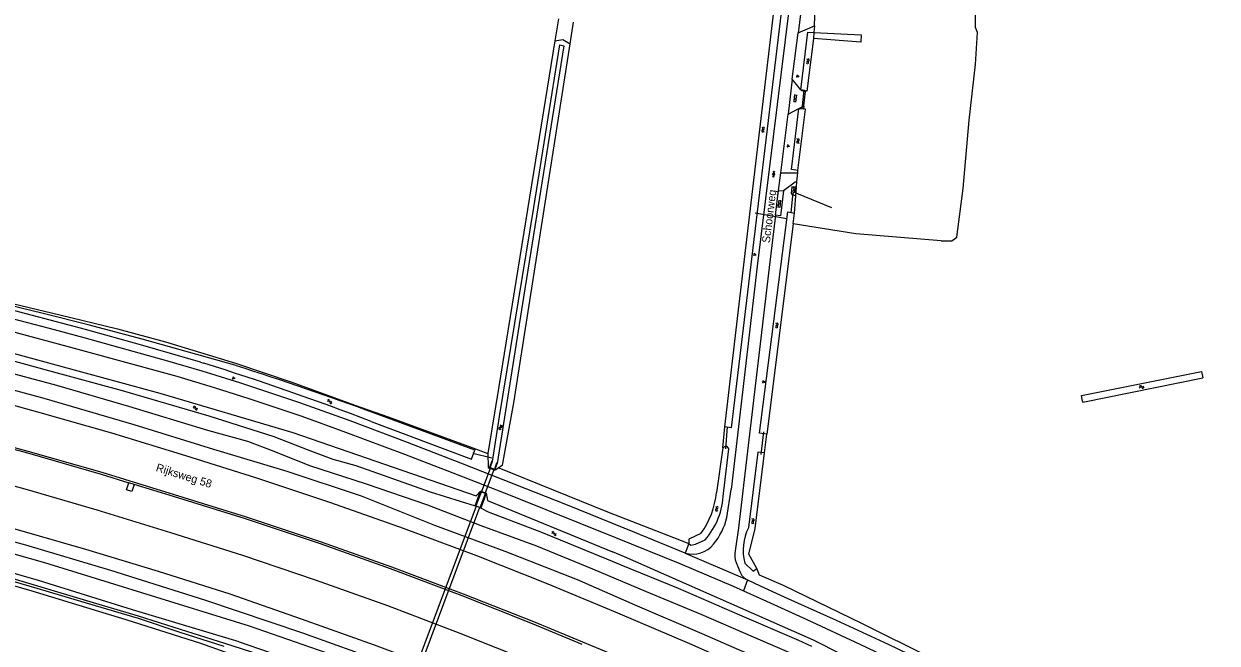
# Model space of a CAD drawing. Extents: x 124000 to 129000, y 395500 to 397503.
# Drawn here: x 125816.2 to 126188.8, y 395694.1 to 395887.3 of the extents above; entities that cross this region are included whole.
import ezdxf

# ---------------------------------------------------------------- set-up
doc = ezdxf.new("R2010")
doc.units = 0
for name, color, linetype in [('gg-anno-openbare ruimte label', 7, 'Continuous'), ('gg-knt-BGT kruinlijn', 7, 'Continuous'), ('gg-knt-bronhoudergrens', 7, 'Continuous'), ('gg-knt-verharding', 7, 'Continuous'), ('gg-kntw-bovenkant insteek waterloop', 7, 'Continuous'), ('gg-kntw-midden sloot', 7, 'Continuous'), ('gg-kntw-waterlijn', 7, 'Continuous'), ('gg-kwrk-duiker nz buis', 7, 'Continuous'), ('gg-kwrk-duiker nz vlak', 7, 'Continuous'), ('gg-kwrk-uitstroombak niveau min 01', 7, 'Continuous'), ('gt-grn-groengrens', 7, 'Continuous'), ('gt-grn-vlakafsluiter', 7, 'Continuous'), ('gt-grn-weggrens', 7, 'Continuous'), ('gt-symb-gesloten verharding', 7, 'Continuous'), ('gt-symb-groenvak', 7, 'Continuous'), ('gt-symb-klinker verharding', 7, 'Continuous'), ('gt-symb-watersymbool', 7, 'Continuous'), ('gx-grn-maaiveld', 7, 'Continuous')]:
    doc.layers.add(name, color=color, linetype=linetype)

# ---------------------------------------------------------------- blocks, each defined once
blk = doc.blocks.new('gt0-WA')
at = {"layer": 'gt-symb-watersymbool'}
for centre, start, end in [((-0.32, 0.02), 28.0725, 151.9275), ((0.43, 0.42), 208.0725, 331.9275), ((-0.32, -0.43), 28.0725, 151.9275), ((0.43, -0.03), 208.0725, 331.9275)]:
    blk.add_arc(centre, 0.425, start, end, dxfattribs=at)
blk = doc.blocks.new('gt0-GESVH1')
at = {"layer": 'gt-symb-gesloten verharding'}
for p, q in [((-0.99, -0.26), (0.01, 0.24)), ((0.01, -0.26), (-0.99, 0.24)), ((0.01, 0.24), (1.01, -0.26)), ((1.01, 0.24), (0.01, -0.26))]:
    blk.add_line(p, q, dxfattribs=at)
blk = doc.blocks.new('gt0-KL1')
at = {"layer": 'gt-symb-klinker verharding'}
for p, q in [((-1.15, 0.3), (1.15, 0.3)), ((-1, -0.3), (-1, 0.3)), ((-0.5, 0.3), (-0.5, 0.45)), ((0, -0.3), (0, 0.3)), ((0.5, 0.3), (0.5, 0.45)), ((1, -0.3), (1, 0.3)), ((-1.15, -0.3), (1.15, -0.3)), ((-0.5, -0.45), (-0.5, -0.3)), ((0.5, -0.45), (0.5, -0.3))]:
    blk.add_line(p, q, dxfattribs=at)
blk = doc.blocks.new('gt0-GRVAK')
at = {"layer": 'gt-symb-groenvak'}
for p, q in [((-0.11, 0.19), (-0.23, 0.24)), ((-0.18, 0.15), (0.09, 0.15)), ((-0.09, 0.21), (-0.16, 0.32)), ((-0.05, 0.21), (-0.05, 0.39)), ((0, 0.21), (0.06, 0.32)), ((0.01, 0.19), (0.13, 0.24)), ((0.26, -0.05), (0.2, 0.06)), ((0.3, -0.05), (0.3, 0.13)), ((0.35, -0.05), (0.41, 0.06)), ((-0.25, -0.23), (-0.36, -0.18)), ((-0.32, -0.26), (-0.05, -0.26)), ((-0.23, -0.21), (-0.29, -0.09)), ((-0.18, -0.2), (-0.18, -0.02)), ((-0.14, -0.21), (-0.07, -0.09)), ((-0.12, -0.23), (0, -0.18)), ((0.24, -0.07), (0.12, -0.02)), ((0.17, -0.11), (0.44, -0.11)), ((0.37, -0.07), (0.49, -0.02))]:
    blk.add_line(p, q, dxfattribs=at)

msp = doc.modelspace()

# ---------------------------------------------------------------- linework, layer by layer
at = {"layer": 'gg-knt-BGT kruinlijn'}
for p, q in [((125822.59, 395770.4), (125795.86, 395777.69)), ((125850.71, 395762.21), (125822.59, 395770.4)), ((125875.54, 395754.47), (125850.71, 395762.21)), ((125898.42, 395747.58), (125875.54, 395754.47)), ((125921.63, 395739.97), (125898.42, 395747.58)), ((125944.56, 395730.8), (125921.63, 395739.97)), ((125789.04, 395732.43), (125816.71, 395724.68)), ((125966.48, 395722.66), (125944.56, 395730.8)), ((125816.71, 395724.68), (125843.28, 395716.78)), ((125989.13, 395713.79), (125966.48, 395722.66)), ((125843.28, 395716.78), (125872.65, 395707.56)), ((126007.81, 395705.61), (125989.13, 395713.79)), ((125872.65, 395707.56), (125903.24, 395697.29)), ((126028.04, 395696.99), (126007.81, 395705.61)), ((125903.24, 395697.29), (125928.73, 395688.16)), ((126048.7, 395687.9), (126028.04, 395696.99))]:
    msp.add_line(p, q, dxfattribs=at)
at = {"layer": 'gg-knt-bronhoudergrens'}
msp.add_line((125957.27, 395754.66), (125961.07, 395753.26), dxfattribs=at)
for points in [[(126102.69, 395819.58), (126106.04, 395819.58), (126107.56, 395820.79), (126109.51, 395835.96), (126111.37, 395857.27), (126113.34, 395874.59), (126114.06, 395884.6), (126113.42, 395886.22), (126113.26, 395895.34), (126112.79, 395909.76), (126111.89, 395937.12), (126111.06, 395945.04), (126108.32, 395960.35), (126108.23, 395966.98), (126109.91, 395986.19), (126113.52, 396011.65), (126116.03, 396020.3), (126113.47, 396019.36), (126109.85, 396016.85), (126103.53, 396016.89), (125991.53, 396037.81), (125965.82, 396042.18), (125959.56, 396043.24)], [(126102.69, 395819.58), (126076.03, 395821.75), (126056.42, 395824.92)], [(125798.26, 395803.49), (125827.46, 395796.47), (125845.5, 395792.11), (125860.48, 395788.1), (125882.33, 395781.38), (125899.9, 395775.5), (125919.63, 395768.34), (125929.95, 395764.7), (125957.27, 395754.66)]]:
    msp.add_lwpolyline(points, dxfattribs=at)
at = {"layer": 'gg-knt-verharding'}
for p, q in [((126059.34, 395895.36), (126058, 395884.57)), ((126063.12, 395886.74), (126063.33, 395892.62)), ((126058, 395884.57), (126063.12, 395886.74)), ((126056.16, 395870.08), (126058, 395884.57)), ((126056.16, 395870.08), (126054.86, 395859.13)), ((126058.88, 395866.76), (126056.16, 395870.08)), ((126059.79, 395861.76), (126060.26, 395866.22)), ((126054.86, 395859.13), (126058.26, 395860.94)), ((126058.26, 395860.94), (126059.79, 395861.76)), ((126052.56, 395840.82), (126054.86, 395859.13)), ((126051.87, 395835.33), (126052.56, 395840.82)), ((126050.91, 395827.64), (126051.87, 395835.33)), ((126051.87, 395835.33), (126053.44, 395835.18)), ((126035.79, 395733.27), (126037.06, 395741.97)), ((126038.61, 395719.2), (126039.8, 395716.41))]:
    msp.add_line(p, q, dxfattribs=at)
for points in [[(126058.95, 395922.83), (126045.22, 395811.68), (126037.06, 395741.97)], [(126060.26, 395866.22), (126059.15, 395866.44), (126058.88, 395866.76)], [(126053.44, 395835.18), (126052.51, 395827.38), (126050.91, 395827.64)], [(126022.76, 395722.11), (126007, 395728.6), (125985.97, 395737.13), (125952.66, 395750.24), (125936, 395756.72), (125918.09, 395763.38), (125902.07, 395769.2), (125883.69, 395775.34), (125871.89, 395778.96), (125861.22, 395782.09), (125835.07, 395789.29), (125824.23, 395792.24), (125804.96, 395797.2), (125777.26, 395804.17), (125755.56, 395809.29), (125733.37, 395814.55), (125716.44, 395818.3), (125699.46, 395821.94), (125681.99, 395825.55), (125674.92, 395827.17)], [(126050.91, 395827.64), (126048.94, 395811.26), (126041.98, 395752.18)], [(125674.16, 395823.57), (125678.1, 395822.72), (125691.05, 395819.88), (125709.53, 395815.85), (125733.94, 395810.48), (125761.83, 395803.89), (125781.88, 395799.05), (125811.81, 395791.48), (125829.69, 395786.75), (125864.03, 395777.32), (125875.66, 395773.83), (125886.45, 395770.43), (125903.06, 395764.84), (125916.64, 395759.93), (125935.13, 395753.05), (125951.53, 395746.7), (125968.05, 395740.21), (126000.96, 395727.02), (126021.04, 395718.9), (126037.7, 395711.82), (126040.95, 395710.35)], [(126041.98, 395752.18), (126039.35, 395730.07), (126038.33, 395722.91)], [(126042.22, 395713.78), (126046.16, 395711.89), (126053.86, 395708.39), (126069.86, 395701.22), (126086.13, 395693.68), (126102.09, 395686.06), (126118, 395678.32), (126133.82, 395670.09), (126149.27, 395661.59), (126164.3, 395653.05), (126189.34, 395638.28), (126200.18, 395631.68), (126215.29, 395622.04), (126230.56, 395612.16), (126245.74, 395602.08), (126260.92, 395591.88), (126271.17, 395584.85)], [(126040.95, 395710.35), (126048.11, 395707.13), (126060.74, 395701.45), (126077.31, 395693.75), (126093.98, 395685.69), (126109.53, 395678.27), (126126.22, 395669.87), (126139.51, 395662.65), (126153.36, 395654.97), (126161.96, 395649.97), (126187.32, 395635.03), (126196.89, 395629.24), (126212.12, 395619.51), (126227.2, 395609.73), (126242.37, 395599.7), (126258.48, 395589), (126274.57, 395578.12), (126291.72, 395566.21), (126306.5, 395555.62), (126321.18, 395545.07), (126335.63, 395534.59), (126349.94, 395523.94), (126363.93, 395513.38), (126381.12, 395500)]]:
    msp.add_lwpolyline(points, dxfattribs=at)
for centre, radius, start, end in [((126014.56, 395738.64), 21.89, 321.1392, 345.8019), ((126024.97, 395730.5), 8.68, 255.2003, 319.8663), ((126044.54, 395721.5), 6.36, 167.26, 201.2253), ((126044.11, 395717.95), 4.57, 199.7248, 245.6922)]:
    msp.add_arc(centre, radius, start, end, dxfattribs=at)
at = {"layer": 'gg-kntw-bovenkant insteek waterloop'}
for p, q in [((126039.64, 395799.84), (126054.41, 395924.58)), ((125982.08, 395882.03), (125964.45, 395773.48)), ((125969.2, 395769.01), (125986.77, 395881.09)), ((126060.29, 395866.41), (126058.88, 395866.76)), ((126058.26, 395860.94), (126059.68, 395860.79)), ((126057.25, 395833.6), (126057.52, 395836.38)), ((126056.42, 395824.92), (126056.84, 395828.28)), ((126056.42, 395824.92), (126048.22, 395759.3)), ((126035.11, 395761.6), (126039.64, 395799.84)), ((125871.36, 395781.7), (125872.46, 395781.38)), ((125882.63, 395780.61), (125882.12, 395780.76)), ((125964.45, 395773.48), (125961.07, 395753.26)), ((125965.7, 395749.62), (125969.2, 395769.01)), ((125957.1, 395754.23), (125925.75, 395765.79)), ((126034.45, 395755.05), (126032.48, 395741.08)), ((125965.7, 395749.62), (125964.5, 395748.78)), ((126027.67, 395728.23), (126023.85, 395726.46)), ((126023.85, 395726.46), (126023.91, 395725.19))]:
    msp.add_line(p, q, dxfattribs=at)
for points in [[(126056.72, 395924.63), (126037.09, 395761.28), (126035.11, 395761.6)], [(126058.88, 395866.76), (126061, 395884.77), (126062.9, 395884.67)], [(126062.81, 395882.77), (126060.67, 395866.32), (126060.29, 395866.41)], [(126062.9, 395884.67), (126077.65, 395883.85), (126077.58, 395881.57), (126062.81, 395882.77)], [(125982.08, 395882.03), (125984.54, 395882.49), (125986.77, 395881.09)], [(126057.94, 395841.59), (126055.92, 395841.84), (126058.26, 395860.94)], [(126057.94, 395841.59), (126060.29, 395860.72), (126059.68, 395860.79)], [(126057.52, 395836.38), (126056.08, 395836.49), (126055.86, 395834.29), (126057.25, 395833.6)], [(126048.22, 395759.3), (126045.99, 395759.61), (126054.83, 395828.62), (126056.84, 395828.28)], [(125740.26, 395802.69), (125777.57, 395794.13), (125858.72, 395772.11), (125900.22, 395759.79), (125957.48, 395739.98), (125958.87, 395741.48)], [(125871.36, 395781.7), (125852.61, 395787.16), (125835.45, 395791.95), (125807.8, 395799.18), (125797.68, 395801.79), (125797.96, 395802.62)], [(125882.12, 395780.76), (125853.21, 395788.96), (125836.27, 395793.39), (125822.22, 395796.95), (125808, 395800.34), (125797.96, 395802.62)], [(126146.82, 395769.61), (126146.48, 395771.3), (126183.98, 395778.82), (126184.38, 395776.8)], [(126146.82, 395769.61), (126146.88, 395769.29), (126184.38, 395776.8)], [(125924.72, 395763.23), (125956.01, 395751.48), (125957.1, 395754.23)], [(125961.07, 395753.26), (125961.23, 395748.83), (125961.56, 395748.7)], [(126034.67, 395740.77), (126036.4, 395754.74), (126035.83, 395755.39), (126035.19, 395755.47), (126034.45, 395755.05)], [(126047.49, 395753.49), (126045.47, 395753.64), (126042.52, 395730.09)], [(126045.11, 395717.31), (126042.65, 395721.84), (126044.59, 395729.81), (126047.49, 395753.49)], [(125964.5, 395748.78), (125963.4, 395748.01), (125963.32, 395748.04)], [(125960.62, 395740.85), (125961.03, 395738.55), (126000, 395722.55)], [(126000, 395719.54), (125977.92, 395728.59), (125961.27, 395734.93), (125958.91, 395736.21)], [(126023.91, 395725.19), (126024.53, 395724.66), (126026, 395724.95), (126028.93, 395726.29)], [(126071.66, 395690.51), (126062.82, 395695.02), (126003.8, 395720.99), (126000, 395722.55)], [(126041.34, 395719.06), (126044, 395716.5), (126045.11, 395717.31)]]:
    msp.add_lwpolyline(points, dxfattribs=at)
for centre, radius, start, end in [((125617.37, 394962.61), 857.59, 68.99873, 72.69556), ((125585.91, 394847.22), 979.42, 69.69725, 72.36461), ((126006.57, 395743.46), 26.02, 324.1732, 354.7499), ((126011.69, 395741.51), 23, 318.5527, 358.1654), ((126056.12, 395723.05), 15.31, 152.6637, 195.1182)]:
    msp.add_arc(centre, radius, start, end, dxfattribs=at)
at = {"layer": 'gg-kntw-midden sloot'}
msp.add_line((126057.48, 395834.51), (126068.43, 395830.01), dxfattribs=at)
at = {"layer": 'gg-kntw-waterlijn'}
for points in [[(125962.54, 395750.73), (125964.76, 395764.81), (125975.48, 395830.02), (125983.63, 395880.76), (125984.89, 395880.42)], [(125984.89, 395880.42), (125972.25, 395801.98), (125964.05, 395750.12)]]:
    msp.add_lwpolyline(points, dxfattribs=at)
at = {"layer": 'gg-kwrk-duiker nz buis'}
for p, q in [((126059.27, 395860.75), (126059.84, 395866.76)), ((126055.8, 395828.5), (126056.49, 395834.54)), ((126054.44, 395826.44), (126044.54, 395828.24)), ((126035.4, 395754.69), (126035.97, 395761.6)), ((126047.21, 395760.03), (126046.35, 395752.95)), ((125956.39, 395753.38), (125962.39, 395751.9))]:
    msp.add_line(p, q, dxfattribs=at)
at = {"layer": 'gg-kwrk-duiker nz vlak'}
for p, q in [((125961.86, 395748.59), (125959.16, 395741.38)), ((125962.98, 395748.16), (125960.29, 395740.97)), ((125957.43, 395736.76), (125934.92, 395676.72)), ((125958.55, 395736.35), (125936.04, 395676.3))]:
    msp.add_line(p, q, dxfattribs=at)
at = {"layer": 'gg-kwrk-uitstroombak niveau min 01'}
for p, q in [((125961.86, 395748.59), (125961.56, 395748.7)), ((125962.98, 395748.16), (125961.86, 395748.59)), ((125963.07, 395748.38), (125961.94, 395748.8)), ((125963.32, 395748.04), (125964.05, 395750.12)), ((125963.32, 395748.04), (125962.98, 395748.16)), ((125957.13, 395736.87), (125958.87, 395741.48)), ((125958.87, 395741.48), (125959.16, 395741.38)), ((125959.16, 395741.38), (125959.72, 395741.17)), ((125959.72, 395741.17), (125960.29, 395740.97)), ((125960.62, 395740.85), (125958.91, 395736.21)), ((125960.29, 395740.97), (125960.62, 395740.85)), ((125957.43, 395736.76), (125957.13, 395736.87)), ((125957.99, 395736.55), (125957.43, 395736.76)), ((125958.55, 395736.35), (125957.99, 395736.55)), ((125958.91, 395736.21), (125958.55, 395736.35))]:
    msp.add_line(p, q, dxfattribs=at)
for points in [[(125962.54, 395750.73), (125962.34, 395750.8), (125961.56, 395748.7)], [(125961.94, 395748.8), (125961.84, 395748.83), (125962.54, 395750.73)], [(125964.05, 395750.12), (125963.86, 395750.19), (125963.18, 395748.34), (125963.07, 395748.38)], [(125957.37, 395736.89), (125958.73, 395736.36), (125960.4, 395740.71), (125959.03, 395741.22), (125957.37, 395736.89)]]:
    msp.add_lwpolyline(points, dxfattribs=at)
at = {"layer": 'gt-grn-groengrens'}
for p, q in [((126063.12, 395886.74), (126062.9, 395884.67)), ((126060.29, 395866.41), (126060.26, 395866.22)), ((126059.79, 395861.76), (126059.68, 395860.79)), ((126057.52, 395836.38), (126057.65, 395837.97)), ((126057.88, 395840.83), (126057.94, 395841.59)), ((126056.84, 395828.28), (126057.25, 395833.6)), ((126034.45, 395755.05), (126035.11, 395761.6)), ((126047.49, 395753.49), (126048.22, 395759.3)), ((125957.27, 395754.66), (125957.1, 395754.23)), ((126019.11, 395727), (126023.91, 395725.19)), ((126023.91, 395725.19), (126022.76, 395722.11)), ((126045.91, 395715.27), (126045.11, 395717.31))]:
    msp.add_line(p, q, dxfattribs=at)
for points in [[(125964.5, 395748.78), (125998.47, 395735.07), (126019.11, 395727)], [(126078.1, 395700.06), (126053.45, 395712.02), (126045.91, 395715.27)], [(126189.61, 395639.6), (126145.33, 395665.34), (126126.97, 395675.17), (126099.69, 395689.31), (126078.1, 395700.06)]]:
    msp.add_lwpolyline(points, dxfattribs=at)
at = {"layer": 'gt-grn-vlakafsluiter'}
for p, q in [((125983.2, 395888.88), (125982.08, 395882.03)), ((125986.77, 395881.09), (125987.84, 395887.89)), ((126062.9, 395884.67), (126062.81, 395882.77))]:
    msp.add_line(p, q, dxfattribs=at)
at = {"layer": 'gt-grn-weggrens'}
for p, q in [((126057.65, 395837.97), (126057.88, 395840.83)), ((126022.76, 395722.11), (126042.22, 395713.78)), ((126042.22, 395713.78), (126040.95, 395710.35))]:
    msp.add_line(p, q, dxfattribs=at)
for points in [[(126052.56, 395840.82), (126057.37, 395840.87), (126057.88, 395840.83)], [(126057.65, 395837.97), (126057.04, 395837.87), (126053.44, 395835.18)]]:
    msp.add_lwpolyline(points, dxfattribs=at)
at = {"layer": 'gx-grn-maaiveld'}
for p, q in [((125850.7, 395743.52), (125848.97, 395744.06)), ((126062.29, 395692.98), (126058.19, 395694.9))]:
    msp.add_line(p, q, dxfattribs=at)
for points in [[(125714.29, 395806.05), (125733.21, 395801.87), (125753.32, 395797.22), (125779.82, 395791), (125801.88, 395785.22), (125823.96, 395779.13), (125846.92, 395772.9), (125873.97, 395764.98), (125894.28, 395758.5), (125905.25, 395754.24), (125912.74, 395751.51), (125919.84, 395749.52), (125943.06, 395741.26), (125957.13, 395736.87)], [(125714.19, 395801.96), (125722.3, 395800.2), (125749.73, 395794.08), (125783.47, 395785.97), (125807.68, 395779.51), (125826.41, 395774.51), (125848.88, 395768), (125873.61, 395760.51), (125886.06, 395757.12), (125894.24, 395753.94), (125905.38, 395749.5), (125923.14, 395743.82), (125942.22, 395737.25), (125958.95, 395730.81), (125976.27, 395724.38), (125993.75, 395717.28), (126010.55, 395710.21), (126027.65, 395703.06), (126043.99, 395696.06), (126061.37, 395688.53), (126061.8, 395688.33)], [(126060.64, 395677.27), (126046.44, 395683.94), (126024.2, 395693.84), (126001.74, 395703.43), (125979.94, 395712.47), (125957.69, 395721.26), (125934.82, 395729.83), (125912.08, 395737.88), (125889, 395745.5), (125866.81, 395752.52), (125843.67, 395759.55), (125820.58, 395766.17), (125798.02, 395772.37), (125774.91, 395778.32), (125751.15, 395784.11), (125728.11, 395789.44), (125713.97, 395792.6)], [(125713.65, 395779.04), (125724.66, 395776.56), (125748.26, 395771.08), (125771.16, 395765.54), (125794.36, 395759.58), (125817.35, 395753.4), (125840.36, 395746.78), (125848.97, 395744.06)], [(125713.67, 395779.77), (125724.88, 395777.26), (125748.46, 395771.75), (125771.36, 395766.21), (125794.58, 395760.19), (125817.5, 395753.95), (125840.54, 395747.42), (125863.19, 395740.49), (125885.65, 395733.44), (125908.79, 395725.8), (125930.98, 395717.84), (125953.38, 395709.45), (125975.41, 395700.76), (125997.45, 395691.67), (126019.39, 395682.27), (126041.01, 395672.57), (126059.25, 395664.07)], [(125713.39, 395767.84), (125724.21, 395765.41), (125746.96, 395760.06), (125770.28, 395754.43), (125793.46, 395748.44), (125816.5, 395742.19), (125839.02, 395735.64), (125862.03, 395728.62), (125884.5, 395721.48), (125907.17, 395713.77), (125929.75, 395705.76), (125952.38, 395697.18), (125974.89, 395688.26), (125997.01, 395679.35), (126018.93, 395669.68), (126040.4, 395659.98), (126057.96, 395651.74)], [(126056.55, 395638.35), (126035.95, 395647.95), (126013.82, 395657.99), (125991.95, 395667.32), (125970.29, 395676.37), (125948.16, 395684.98), (125925.73, 395693.44), (125902.94, 395701.52), (125880.64, 395709.29), (125858.24, 395716.4), (125835.55, 395723.29), (125813.56, 395729.59), (125790.41, 395736.01), (125766.96, 395741.97), (125744.08, 395747.44), (125732.19, 395750.11), (125713.06, 395753.85)], [(125891.45, 395687.34), (125882.36, 395690.09), (125871.46, 395693.97), (125848.15, 395701.33), (125818.85, 395710.28), (125809.84, 395712.88), (125791.22, 395718.26), (125761.11, 395726.08), (125738.21, 395731.47), (125717.24, 395735.86), (125712.65, 395736.68), (125695.26, 395739.83), (125672.53, 395743.48), (125653.6, 395746.62)], [(125712.87, 395745.87), (125729.56, 395742.46), (125763.86, 395735.14), (125793.12, 395727.53), (125822.65, 395719.17), (125852.93, 395709.87), (125886.62, 395699.44), (125912.96, 395690.27), (125943.81, 395679.56), (125970.87, 395668.96), (125998.93, 395656.32), (126003.25, 395654.3), (126006.92, 395651.8), (126018.27, 395645.97), (126033.37, 395639.08), (126043.95, 395634.09), (126055.5, 395628.34)], [(125850.7, 395743.52), (125849.97, 395741.38), (125848.28, 395741.88), (125848.97, 395744.06)], [(125990.6, 395693.63), (125975.1, 395700.09), (125953.14, 395708.78), (125930.7, 395717.27), (125908.57, 395725.11), (125885.4, 395732.81), (125863, 395739.82), (125850.7, 395743.52)], [(125883.43, 395694.48), (125850.17, 395704.49), (125820.85, 395713.55), (125789.65, 395722.51), (125764.5, 395729.35), (125738.65, 395735.58), (125714.64, 395740.44)], [(126058.19, 395694.9), (126039.85, 395702.78), (126020.6, 395711.09), (126002.77, 395718.43), (126002.56, 395718.52), (126000, 395719.54)], [(125804.48, 395715.79), (125820.26, 395711.16), (125836.68, 395706.31), (125851.89, 395701.8), (125864.9, 395697.49), (125878.63, 395693.07)], [(125935.14, 395676.64), (125934.76, 395676.11), (125934.35, 395675.75), (125933.64, 395675.56), (125933.03, 395675.53), (125923.47, 395678.71), (125908.95, 395684.05), (125892.98, 395689.46), (125878.95, 395693.99), (125865.11, 395698.31), (125852.06, 395702.48), (125836.89, 395706.95), (125820.61, 395711.87), (125804.74, 395716.54)], [(125883.43, 395694.48), (125933.92, 395677.06), (125934.47, 395676.87)]]:
    msp.add_lwpolyline(points, dxfattribs=at)

# ---------------------------------------------------------------- block references
at = {"layer": 'gt-symb-gesloten verharding', "rotation": -96.83367234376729}
msp.add_blockref('gt0-GESVH1', (126050.4, 395840.42), dxfattribs=at)
at = {"layer": 'gt-symb-groenvak'}
for p in [(126057.82, 395871.03), (126054.87, 395849.24), (126044.42, 395815.37), (125881.67, 395776.81), (126047.2, 395775.65)]:
    msp.add_blockref('gt0-GRVAK', p, dxfattribs=at)
at = {"layer": 'gt-symb-klinker verharding'}
for p, rotation in [((126057.07, 395864.1), -96.83367234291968), ((126052.11, 395831.15), -96.83367234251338)]:
    msp.add_blockref('gt0-KL1', p, dxfattribs=dict(at, rotation=rotation))
at = {"layer": 'gt-symb-watersymbool'}
for p, rotation in [((126061.06, 395875.67), -82.12907949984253), ((126047.08, 395854.37), -82.12907949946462), ((126057.96, 395850.83), -82.12907949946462), ((126056.77, 395835.48), -82.12907950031), ((126051.36, 395793.25), -82.12907949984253), ((126165.18, 395774.01), 11.366137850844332), ((125869.76, 395767.41), -16.858398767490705), ((125911.67, 395769.45), -16.858398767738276), ((125965.07, 395761.32), 78.70129979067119), ((126032.59, 395736.05), -82.12907949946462), ((126043.86, 395732.18), -82.12907950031), ((125981.73, 395728.26), -16.858398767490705)]:
    msp.add_blockref('gt0-WA', p, dxfattribs=dict(at, rotation=rotation))

# ---------------------------------------------------------------- texts
at = {"layer": 'gg-anno-openbare ruimte label'}
for s, rotation, p in [('Schoorweg', 83.1, (126049.17, 395818.82)), ('Rijksweg 58', 342.7, (125857.27, 395747.81))]:
    msp.add_text(s, height=2.5, rotation=rotation, dxfattribs=at).set_placement(p)

doc.saveas('drawing.dxf')
